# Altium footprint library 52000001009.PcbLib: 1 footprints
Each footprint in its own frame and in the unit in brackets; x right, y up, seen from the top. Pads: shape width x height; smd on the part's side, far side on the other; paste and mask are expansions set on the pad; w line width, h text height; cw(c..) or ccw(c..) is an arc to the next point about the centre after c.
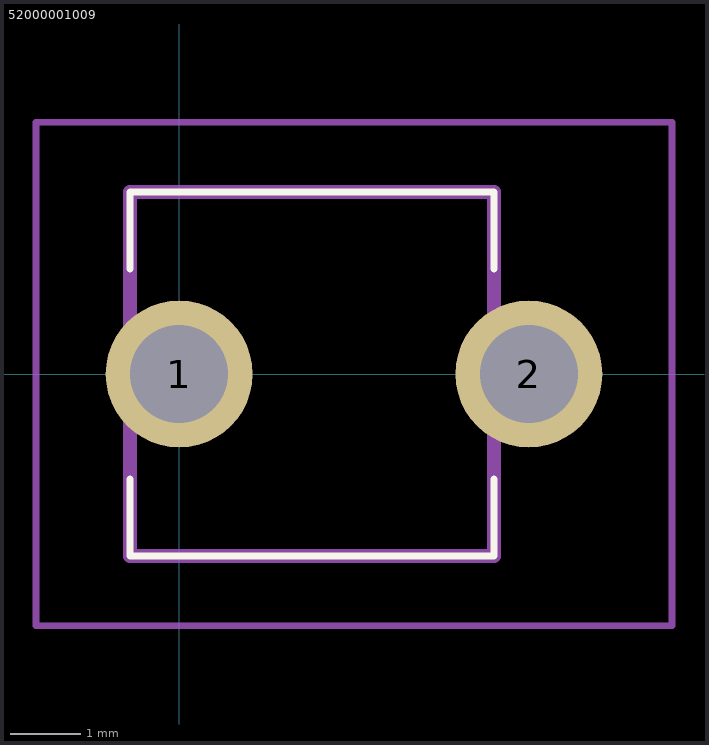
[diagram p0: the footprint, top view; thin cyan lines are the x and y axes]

## 52000001009 [mm]
pads (2):
  round 2.1 hole 1.4: 1(0,0) 2(5,0)
Top Overlay:
  lines w0.1: -0.7,-1.5 -0.7,-2.6 4.5,-2.6 4.5,-1.5 ; -0.7,1.5 -0.7,2.6 4.5,2.6 4.5,1.5
Mechanical 15:
  lines w0.2: -0.7,-2.6 4.5,-2.6 4.5,2.6 -0.7,2.6 -0.7,-2.6
Mechanical 20:
  lines w0.1: -2.05,-3.6 7.05,-3.6 7.05,3.6 -2.05,3.6 -2.05,-3.6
